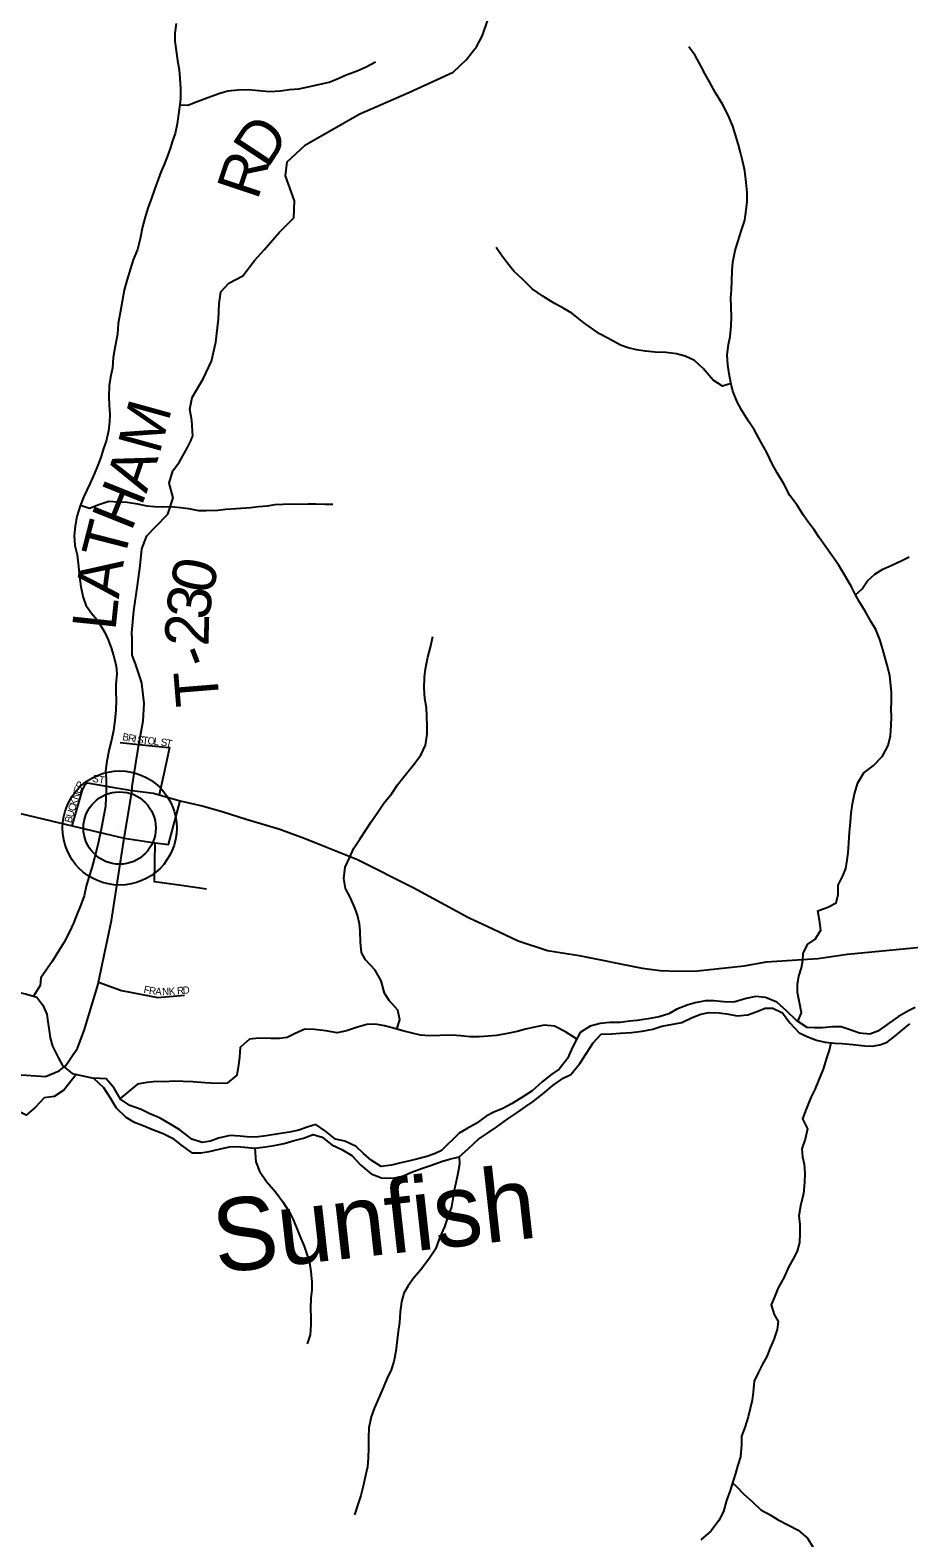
# Model space of a CAD drawing. Extents: x 1578669 to 1989827, y 208020 to 553079.
# Drawn here: x 1755983 to 1762031, y 396225 to 406595 of the extents above; entities that cross this region are included whole.
import ezdxf

# ---------------------------------------------------------------- set-up
doc = ezdxf.new("R2010")
doc.units = 0
for name, color, linetype in [('GM_X_County_Road', 7, 'Continuous'), ('GM_X_Minor_River', 7, 'Continuous'), ('GM_X_Minor_River_Text', 7, 'Continuous'), ('GM_X_State_Route', 7, 'Continuous'), ('GM_X_Township_Road', 7, 'Continuous'), ('GM_X_Township_Road_Text', 7, 'Continuous'), ('GM_X_Township_ROW', 7, 'Continuous'), ('GM_X_Township_Subdivision', 7, 'Continuous'), ('GM_X_Township_Subdivision_Text', 7, 'Continuous'), ('GM_X_Unincorporated', 7, 'Continuous'), ('GM_X_Unincorporated_Location', 7, 'Continuous')]:
    doc.layers.add(name, color=color, linetype=linetype)

msp = doc.modelspace()

# ---------------------------------------------------------------- linework, layer by layer
at = {"layer": 'GM_X_County_Road'}
msp.add_lwpolyline([(1753586, 396122), (1753678, 396371), (1753785, 396549), (1754239, 397315), (1754508, 397807), (1754696, 398083), (1754951, 398513), (1755274, 399058), (1755432, 399305), (1755508, 399405), (1755564, 399441), (1755766, 399415), (1755956, 399407), (1756090, 399399), (1756182, 399436), (1756228, 399474), (1756266, 399528), (1756310, 399592), (1756355, 399714), (1756451, 400033), (1756454, 400046), (1756543, 400472), (1756630, 401037)], dxfattribs=at)
at = {"layer": 'GM_X_Minor_River'}
for points in [[(1756989, 406641), (1756979, 406575), (1756980, 406519), (1756988, 406453), (1756998, 406387), (1757008, 406322), (1757013, 406262), (1757017, 406194), (1757017, 406122), (1757011, 406064), (1757003, 406002), (1756996, 405950), (1756982, 405883), (1756964, 405833), (1756946, 405781), (1756926, 405723), (1756906, 405671), (1756883, 405619), (1756839, 405499), (1756815, 405433), (1756795, 405377), (1756776, 405317), (1756756, 405241), (1756740, 405159), (1756722, 405087), (1756692, 405015), (1756673, 404956), (1756649, 404872), (1756631, 404806), (1756602, 404650), (1756590, 404578), (1756584, 404504), (1756568, 404422), (1756555, 404344), (1756549, 404273), (1756537, 404209), (1756527, 404151), (1756525, 404073), (1756528, 404015), (1756532, 403951), (1756530, 403901), (1756522, 403839), (1756506, 403768), (1756489, 403718), (1756469, 403656), (1756445, 403592), (1756423, 403540), (1756393, 403474), (1756352, 403388), (1756328, 403324), (1756304, 403250), (1756294, 403184), (1756287, 403116), (1756291, 403050), (1756307, 402985), (1756317, 402905), (1756323, 402835), (1756332, 402765), (1756348, 402693), (1756366, 402640), (1756404, 402588), (1756445, 402538), (1756497, 402452), (1756521, 402401), (1756541, 402347), (1756557, 402293), (1756576, 402223), (1756580, 402167), (1756572, 402095), (1756574, 402040), (1756575, 401988), (1756573, 401918), (1756567, 401846), (1756557, 401778), (1756543, 401712), (1756528, 401650), (1756510, 401566), (1756502, 401497), (1756506, 401445)], [(1760659, 406240), (1760629, 406292), (1760599, 406349), (1760559, 406421), (1760516, 406481)], [(1757013, 406081), (1757069, 406080), (1757133, 406105), (1757205, 406131), (1757289, 406161), (1757343, 406177), (1757415, 406185), (1757485, 406186), (1757579, 406178), (1757633, 406174), (1757703, 406178), (1757767, 406186), (1757833, 406191), (1757897, 406205), (1757967, 406221), (1758041, 406237), (1758107, 406265), (1758159, 406287), (1758233, 406316), (1758295, 406342), (1758361, 406376)], [(1761267, 399777), (1761291, 399836), (1761277, 399906), (1761265, 399975), (1761265, 400031), (1761273, 400089), (1761292, 400145), (1761300, 400195), (1761304, 400247), (1761336, 400309), (1761386, 400343), (1761424, 400405), (1761415, 400473), (1761405, 400537), (1761473, 400563), (1761531, 400593), (1761545, 400649), (1761545, 400715), (1761576, 400779), (1761596, 400829), (1761606, 400886), (1761612, 400936), (1761618, 401002), (1761623, 401078), (1761629, 401148), (1761633, 401208), (1761643, 401274), (1761657, 401342), (1761680, 401418), (1761720, 401486), (1761786, 401534), (1761848, 401602), (1761888, 401674), (1761905, 401742), (1761909, 401815), (1761911, 401871), (1761909, 401925), (1761911, 401977), (1761912, 402039), (1761900, 402155), (1761882, 402226), (1761851, 402334), (1761831, 402404), (1761803, 402472), (1761771, 402525), (1761730, 402599), (1761688, 402665), (1761660, 402715), (1761636, 402765), (1761594, 402836), (1761547, 402918), (1761503, 402980), (1761453, 403051), (1761413, 403105), (1761378, 403157), (1761340, 403209), (1761304, 403262), (1761262, 403328), (1761211, 403394), (1761169, 403475), (1761125, 403549), (1761089, 403613), (1761052, 403689), (1761012, 403764), (1760968, 403844), (1760927, 403906), (1760881, 403979), (1760849, 404039), (1760819, 404111), (1760806, 404169), (1760794, 404231), (1760784, 404292), (1760780, 404362), (1760790, 404432), (1760801, 404488), (1760807, 404562), (1760809, 404622), (1760807, 404692), (1760805, 404753), (1760810, 404809), (1760812, 404871), (1760814, 404941), (1760820, 404999), (1760835, 405079), (1760855, 405145), (1760877, 405213), (1760901, 405289), (1760911, 405356), (1760918, 405414), (1760918, 405478), (1760910, 405546), (1760902, 405628), (1760889, 405688), (1760871, 405753), (1760859, 405805), (1760835, 405881), (1760819, 405935), (1760788, 406009), (1760748, 406086), (1760700, 406164), (1760659, 406240)], [(1760807, 404164), (1760747, 404145), (1760684, 404188), (1760616, 404268), (1760556, 404322), (1760490, 404353), (1760432, 404369), (1760359, 404377), (1760285, 404379), (1760219, 404386), (1760155, 404396), (1760099, 404410), (1760047, 404428), (1759959, 404477), (1759901, 404507), (1759846, 404545), (1759792, 404585), (1759712, 404648), (1759656, 404680), (1759584, 404720), (1759511, 404765), (1759439, 404815), (1759375, 404879), (1759313, 404938), (1759267, 404994), (1759224, 405050), (1759190, 405101)], [(1756329, 403327), (1756392, 403306), (1756456, 403332), (1756524, 403355), (1756588, 403351), (1756652, 403349), (1756722, 403337), (1756786, 403323), (1756838, 403318), (1756892, 403316), (1756952, 403318), (1757018, 403312), (1757072, 403304), (1757141, 403291), (1757195, 403291), (1757275, 403293), (1757329, 403299), (1757401, 403304), (1757499, 403312), (1757555, 403318), (1757617, 403324), (1757669, 403332), (1757725, 403335), (1757781, 403337), (1757843, 403335), (1757897, 403337), (1757951, 403337), (1758013, 403335), (1758067, 403334)], [(1761663, 402711), (1761710, 402751), (1761746, 402807), (1761796, 402853), (1761852, 402887), (1761914, 402915), (1761983, 402947), (1762033, 402973)], [(1758506, 399724), (1758527, 399787), (1758513, 399855), (1758455, 399920), (1758423, 399970), (1758398, 400056), (1758358, 400130), (1758290, 400201), (1758264, 400251), (1758257, 400321), (1758255, 400397), (1758249, 400447), (1758235, 400508), (1758217, 400558), (1758188, 400626), (1758154, 400690), (1758142, 400759), (1758152, 400837), (1758181, 400901), (1758211, 400969), (1758251, 401031), (1758291, 401089), (1758329, 401149), (1758377, 401215), (1758418, 401279), (1758472, 401345), (1758512, 401403), (1758556, 401459), (1758622, 401541), (1758673, 401609), (1758703, 401677), (1758715, 401753), (1758715, 401809), (1758713, 401873), (1758710, 401933), (1758700, 401997), (1758694, 402070), (1758698, 402144), (1758705, 402202), (1758721, 402282), (1758739, 402350), (1758755, 402424)], [(1756506, 401445), (1756507, 401371), (1756505, 401317), (1756501, 401255), (1756491, 401195), (1756475, 401111), (1756450, 400991), (1756426, 400902), (1756408, 400834), (1756388, 400768), (1756369, 400708), (1756355, 400640), (1756333, 400578), (1756303, 400506), (1756281, 400452), (1756254, 400392), (1756218, 400322), (1756184, 400266), (1756134, 400188), (1756098, 400136), (1756057, 400076), (1756053, 400024), (1756007, 399950)], [(1755705, 399995), (1755777, 399991), (1755829, 399986), (1755899, 399978), (1755951, 399966), (1756029, 399944), (1756071, 399889), (1756097, 399827), (1756106, 399773), (1756114, 399715), (1756122, 399663), (1756138, 399607), (1756176, 399528), (1756205, 399474), (1756273, 399418), (1756419, 399387)], [(1762074, 399872), (1762024, 399848), (1761960, 399810), (1761898, 399768), (1761818, 399710), (1761762, 399688), (1761690, 399695), (1761620, 399721), (1761564, 399739), (1761506, 399739), (1761436, 399732), (1761382, 399732), (1761330, 399736), (1761258, 399782), (1761191, 399847), (1761121, 399909), (1761045, 399941), (1760977, 399948), (1760911, 399934), (1760827, 399910), (1760757, 399912), (1760689, 399918), (1760631, 399919), (1760561, 399905), (1760511, 399891), (1760433, 399861), (1760379, 399829), (1760311, 399809), (1760237, 399794), (1760161, 399782), (1760107, 399778), (1760043, 399770), (1759973, 399770), (1759905, 399763), (1759837, 399743), (1759769, 399701), (1759735, 399637), (1759709, 399583), (1759681, 399521), (1759625, 399449), (1759573, 399415), (1759508, 399361), (1759438, 399299), (1759366, 399253), (1759296, 399209), (1759236, 399178), (1759174, 399152), (1759122, 399124), (1759052, 399074), (1758990, 399040), (1758936, 399008), (1758815, 398888)], [(1756419, 399387), (1756487, 399323), (1756534, 399252), (1756576, 399182), (1756642, 399118), (1756694, 399086), (1756762, 399061), (1756831, 399031), (1756899, 399005), (1756963, 398974), (1757023, 398926), (1757097, 398872), (1757159, 398872), (1757215, 398881), (1757285, 398899), (1757355, 398915), (1757407, 398917), (1757458, 398911), (1757530, 398904), (1757604, 398914), (1757674, 398926), (1757732, 398936), (1757800, 398958), (1757864, 398974), (1757930, 398999), (1757992, 398981), (1758060, 398927), (1758128, 398895), (1758196, 398854), (1758259, 398788), (1758329, 398728), (1758401, 398701), (1758479, 398699), (1758545, 398713), (1758615, 398743), (1758677, 398764), (1758745, 398788), (1758815, 398814), (1758869, 398830), (1758935, 398846), (1759001, 398902), (1759069, 398966), (1759138, 399013), (1759194, 399051), (1759270, 399107), (1759332, 399149), (1759394, 399191), (1759446, 399225), (1759510, 399277), (1759580, 399337), (1759652, 399387), (1759704, 399412), (1759767, 399488), (1759813, 399558), (1759859, 399630), (1759913, 399690), (1759985, 399692), (1760043, 399696), (1760121, 399700), (1760195, 399710), (1760269, 399723), (1760331, 399745), (1760395, 399755), (1760469, 399769), (1760539, 399803), (1760599, 399826), (1760653, 399838), (1760723, 399836), (1760777, 399828), (1760849, 399816), (1760923, 399823), (1760973, 399841), (1761041, 399867), (1761095, 399869), (1761161, 399835), (1761212, 399768), (1761276, 399698), (1761336, 399670), (1761394, 399648), (1761454, 399633), (1761520, 399627), (1761572, 399625), (1761644, 399617), (1761728, 399608), (1761779, 399606), (1761831, 399616), (1761881, 399634), (1761932, 399674), (1761986, 399718), (1762038, 399760)], [(1759746, 399658), (1759743, 399657), (1759667, 399705), (1759592, 399744), (1759520, 399750), (1759444, 399736), (1759392, 399724), (1759336, 399708), (1759268, 399693), (1759192, 399679), (1759136, 399675), (1759074, 399671), (1759010, 399671), (1758948, 399678), (1758886, 399682), (1758804, 399680), (1758732, 399678), (1758670, 399682), (1758612, 399695), (1758548, 399711), (1758474, 399733), (1758423, 399747), (1758359, 399758), (1758301, 399756), (1758235, 399738), (1758161, 399712), (1758095, 399698), (1758017, 399711), (1757941, 399721), (1757873, 399723), (1757803, 399691), (1757751, 399667), (1757699, 399660), (1757639, 399660), (1757557, 399662), (1757493, 399654), (1757429, 399598), (1757423, 399532), (1757418, 399478), (1757406, 399408), (1757340, 399352), (1757266, 399350), (1757188, 399355), (1757102, 399361), (1757036, 399363), (1756972, 399365), (1756910, 399362), (1756852, 399364), (1756786, 399356), (1756721, 399346), (1756602, 399246)], [(1761493, 399630), (1761484, 399587), (1761463, 399525), (1761441, 399449), (1761409, 399371), (1761383, 399309), (1761357, 399253), (1761324, 399173), (1761298, 399107), (1761332, 399038), (1761316, 398968), (1761295, 398900), (1761299, 398846), (1761309, 398794), (1761315, 398732), (1761313, 398670), (1761306, 398592), (1761286, 398519), (1761274, 398439), (1761280, 398381), (1761280, 398317), (1761277, 398257), (1761261, 398197), (1761231, 398139), (1761203, 398087), (1761173, 398017), (1761132, 397945), (1761108, 397887), (1761084, 397827), (1761104, 397762), (1761130, 397712), (1761125, 397658), (1761101, 397590), (1761077, 397532), (1761053, 397472), (1761023, 397420), (1760993, 397360), (1760966, 397302), (1760960, 397226), (1760952, 397172), (1760938, 397114), (1760924, 397057), (1760901, 396983), (1760879, 396923), (1760879, 396867), (1760871, 396783), (1760851, 396717), (1760838, 396667), (1760822, 396617), (1760800, 396551), (1760776, 396481), (1760756, 396407), (1760723, 396343), (1760669, 396273), (1760599, 396211)], [(1756301, 399412), (1756215, 399304), (1756149, 399260), (1756079, 399252), (1756019, 399186), (1755956, 399132), (1755887, 399166), (1755815, 399169), (1755751, 399135), (1755700, 399107)], [(1758815, 398888), (1758765, 398866), (1758713, 398848), (1758651, 398831), (1758597, 398817), (1758535, 398803), (1758471, 398789), (1758399, 398779), (1758330, 398822), (1758278, 398868), (1758226, 398916), (1758150, 398953), (1758084, 398967), (1758016, 399023), (1757949, 399067), (1757889, 399050), (1757833, 399028), (1757767, 399016), (1757693, 399004), (1757607, 398990), (1757553, 398983), (1757497, 398981), (1757429, 398987), (1757359, 398991), (1757279, 398973), (1757225, 398952), (1757167, 398944), (1757095, 398966), (1757013, 399030), (1756955, 399065), (1756878, 399111), (1756802, 399143), (1756748, 399170), (1756670, 399198), (1756604, 399242), (1756561, 399317), (1756507, 399381), (1756419, 399387)], [(1757530, 398904), (1757536, 398812), (1757562, 398746), (1757610, 398676), (1757671, 398605), (1757723, 398535), (1757767, 398465), (1757793, 398415), (1757822, 398340), (1757846, 398284), (1757870, 398230), (1757888, 398176), (1757905, 398118), (1757915, 398057), (1757921, 397983), (1757921, 397931), (1757915, 397873), (1757912, 397803), (1757914, 397739), (1757916, 397689), (1757910, 397622), (1757890, 397560)], [(1758936, 398846), (1758937, 398796), (1758927, 398730), (1758913, 398667), (1758902, 398615), (1758892, 398557), (1758882, 398501), (1758856, 398425), (1758834, 398365), (1758803, 398293), (1758773, 398211), (1758727, 398141), (1758669, 398065), (1758623, 398013), (1758584, 397959), (1758556, 397907), (1758540, 397847), (1758530, 397779), (1758524, 397707), (1758517, 397643), (1758509, 397586), (1758499, 397508), (1758485, 397438), (1758467, 397380), (1758440, 397322), (1758406, 397240), (1758380, 397182), (1758350, 397114), (1758330, 397056), (1758315, 396982), (1758311, 396912), (1758311, 396844), (1758309, 396773), (1758304, 396713), (1758292, 396653), (1758276, 396581), (1758260, 396517), (1758238, 396453), (1758215, 396383)], [(1760817, 396602), (1760844, 396579), (1760894, 396526), (1760956, 396470), (1761011, 396418), (1761077, 396384), (1761131, 396349), (1761203, 396311), (1761269, 396277), (1761332, 396222), (1761372, 396158), (1761416, 396082), (1761484, 396017), (1761537, 395973), (1761583, 395921), (1761633, 395865), (1761699, 395802), (1761765, 395734), (1761896, 395609)]]:
    msp.add_lwpolyline(points, dxfattribs=at)
at = {"layer": 'GM_X_State_Route'}
msp.add_lwpolyline([(1753739, 401724), (1756272, 401121), (1756630, 401037), (1756686, 401366), (1756832, 401346), (1756870, 401336), (1757015, 401294), (1757176, 401257), (1757312, 401219), (1757469, 401168), (1757694, 401101), (1757875, 401036), (1758018, 400977), (1758236, 400890), (1758623, 400695), (1758999, 400492), (1759168, 400414), (1759342, 400332), (1759543, 400265), (1759761, 400230), (1760194, 400144), (1760320, 400127), (1760440, 400123), (1760576, 400124), (1760898, 400159), (1761051, 400186), (1761404, 400210), (1761609, 400240), (1762230, 400300)], dxfattribs=at)
at = {"layer": 'GM_X_Township_Road'}
for points in [[(1759025, 406443), (1759054, 406480), (1759097, 406559), (1759134, 406665), (1759141, 406736), (1759142, 406752), (1759144, 406771)], [(1757096, 403788), (1757103, 403803), (1757096, 403909), (1757083, 403988), (1757098, 404068), (1757173, 404197), (1757231, 404317), (1757262, 404449), (1757280, 404606), (1757283, 404714), (1757296, 404796), (1757350, 404854), (1757447, 404905), (1757528, 405010), (1757593, 405084), (1757698, 405203), (1757798, 405304), (1757803, 405420), (1757741, 405592), (1757752, 405688), (1757879, 405807), (1758251, 406019), (1758589, 406166), (1758895, 406305), (1758986, 406394), (1759025, 406443)], [(1756684, 402431), (1756684, 402449), (1756696, 402601), (1756722, 402774), (1756741, 402910), (1756752, 403028), (1756787, 403116), (1756846, 403178), (1756931, 403265), (1756968, 403377), (1756939, 403480), (1756966, 403564), (1757011, 403625), (1757066, 403725), (1757088, 403771), (1757096, 403788)], [(1756742, 402134), (1756708, 402236), (1756686, 402296), (1756685, 402424), (1756684, 402431)], [(1756686, 401366), (1756685, 401393), (1756732, 401682), (1756760, 401844), (1756769, 401964), (1756752, 402103), (1756743, 402132), (1756742, 402134)]]:
    msp.add_lwpolyline(points, dxfattribs=at)
at = {"layer": 'GM_X_Township_ROW'}
msp.add_lwpolyline([(1757196, 400686), (1757025, 400711)], dxfattribs=at)
at = {"layer": 'GM_X_Township_Subdivision'}
for points in [[(1756602, 401696), (1756732, 401682), (1756938, 401661), (1756938, 401661)], [(1756938, 401661), (1756943, 401660), (1756907, 401501), (1756907, 401500)], [(1756907, 401500), (1756870, 401336)], [(1756272, 401121), (1756344, 401369), (1756363, 401405), (1756375, 401417), (1756548, 401389), (1756686, 401366)], [(1756630, 401037), (1756844, 401006), (1756935, 400993), (1757015, 401294)], [(1757025, 400711), (1757025, 400711), (1756838, 400737), (1756844, 401006)], [(1756454, 400046), (1756611, 399989), (1756862, 399942), (1757046, 399958)]]:
    msp.add_lwpolyline(points, dxfattribs=at)
at = {"layer": 'GM_X_Unincorporated'}
for radius in [393, 249]:
    msp.add_circle((1756599, 401107), radius, dxfattribs=at)
at = {"layer": 'GM_X_Unincorporated_Location'}
msp.add_line((1756599, 401107), (1756599, 401107), dxfattribs=at)

# ---------------------------------------------------------------- texts
at = {"layer": 'GM_X_Minor_River_Text'}
msp.add_text('Sunfish', height=500, rotation=6.3488, dxfattribs=at).set_placement((1757268, 398045))
at = {"layer": 'GM_X_Township_Road_Text'}
for s, rotation, p in [('D', 56.6797, (1757615, 405635)), ('R', 71.6934, (1757547, 405420)), ('M', 74.5907, (1756872, 403671)), ('A', 71.5284, (1756783, 403403)), ('H', 68.248, (1756679, 403141)), ('T', 75.6218, (1756626, 402933)), ('A', 82.3346, (1756593, 402680)), ('0', 78.0001, (1757237, 402708)), ('3', 82.6633, (1757214, 402532)), ('L', 84.0578, (1756570, 402460)), ('2', 88.475, (1757210, 402355)), ('-', 111.0927, (1757249, 402271)), ('T', 94.6423, (1757288, 401956))]:
    msp.add_text(s, height=300, rotation=rotation, dxfattribs=at).set_placement(p)
at = {"layer": 'GM_X_Township_Subdivision_Text'}
for s, rotation, p in [('B', 349.5474, (1756615, 401712)), ('R', 349.5727, (1756654, 401705)), ('I', 349.5388, (1756693, 401698)), ('S', 351.7182, (1756717, 401693)), ('T', 353.7656, (1756754, 401688)), ('O', 353.7153, (1756789, 401684)), ('L', 353.7021, (1756832, 401679)), ('S', 353.7018, (1756880, 401674)), ('T', 345.6125, (1756914, 401671)), ('R', 61.3818, (1756337, 401371)), ('ST', 349.3853, (1756408, 401426)), ('N', 73.0399, (1756314, 401298)), ('E', 72.1439, (1756327, 401340)), ('U', 73.0537, (1756277, 401176)), ('C', 73.0472, (1756290, 401218)), ('K', 73.0399, (1756302, 401256)), ('B', 73.0472, (1756266, 401138)), ('F', 347.4703, (1756761, 399975)), ('R', 350.3367, (1756798, 399967)), ('A', 356.0695, (1756843, 399960)), ('N', 1.8024, (1756892, 399957)), ('K', 4.6688, (1756939, 399958)), ('R', 4.6688, (1756996, 399963)), ('D', 4.6688, (1757035, 399966))]:
    msp.add_text(s, height=50, rotation=rotation, dxfattribs=at).set_placement(p)

doc.saveas('drawing.dxf')
